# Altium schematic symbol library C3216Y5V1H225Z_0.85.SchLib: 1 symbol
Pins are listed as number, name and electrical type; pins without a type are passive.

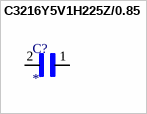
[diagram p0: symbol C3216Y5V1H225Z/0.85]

## C3216Y5V1H225Z/0.85
designator C?
CAPACITOR CERAMIC, 2.2UF, 50V, Y5V, +80,-20%, 1206; MP: C3216Y5V1H225Z/0.85
footprint CAPC3216X180
pins: 1, 2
